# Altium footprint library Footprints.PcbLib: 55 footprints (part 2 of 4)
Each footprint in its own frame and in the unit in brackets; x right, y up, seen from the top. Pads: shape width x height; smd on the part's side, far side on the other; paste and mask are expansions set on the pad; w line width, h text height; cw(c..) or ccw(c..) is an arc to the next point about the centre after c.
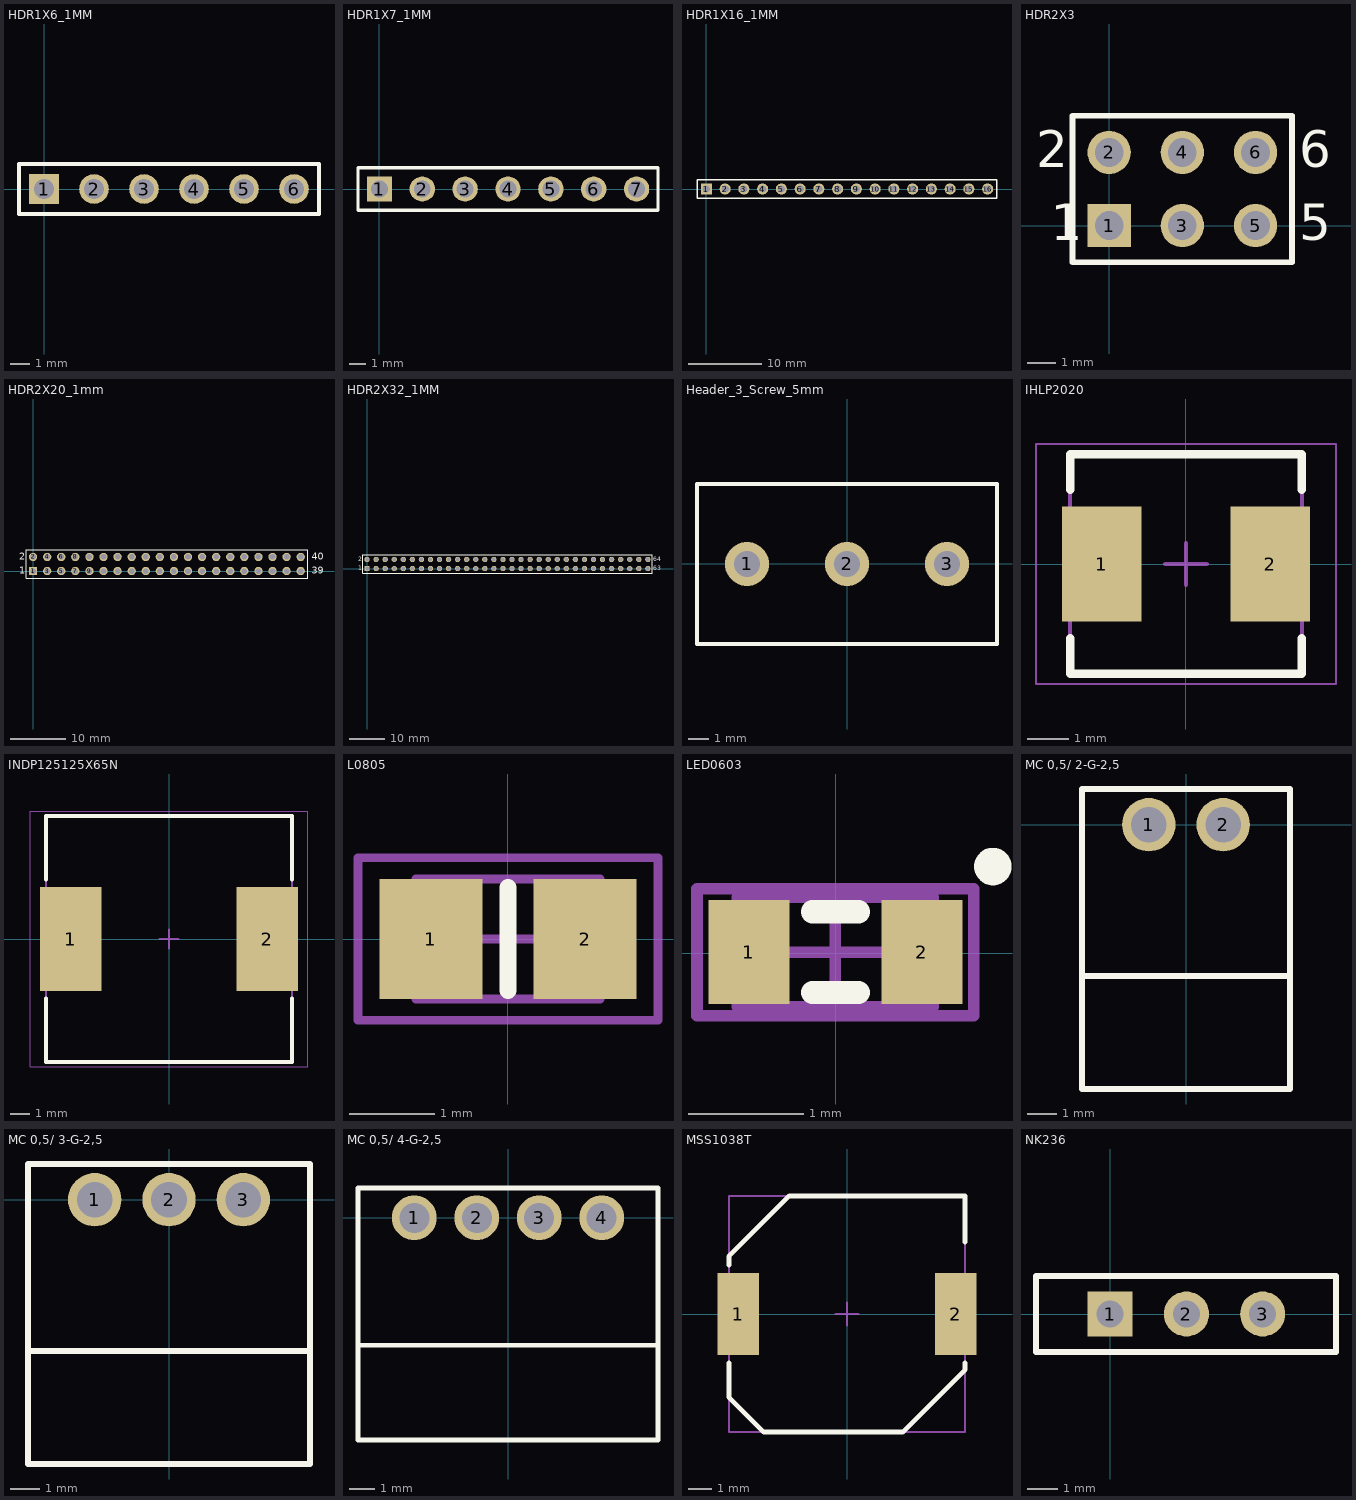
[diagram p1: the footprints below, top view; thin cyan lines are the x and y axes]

## HDR1X6_1MM [mm] "Connector; Header; 6 Position"
pads (6):
  rect 1.5x1.5 hole 1: 1(0,0)
  round 1.5 hole 1: 2(2.54,0) 3(5.08,0) 4(7.62,0) 5(10.16,0) 6(12.7,0)
Top Overlay:
  lines w0.2: -1.27,-1.27 13.97,-1.27 13.97,1.27 -1.27,1.27 -1.27,-1.27

## HDR1X7_1MM [mm] "Connector; Header; 7 Position"
pads (7):
  rect 1.5x1.5 hole 1: 1(0,0)
  round 1.5 hole 1: 2(2.54,0) 3(5.08,0) 4(7.62,0) 5(10.16,0) 6(12.7,0) 7(15.24,0)
Top Overlay:
  lines w0.2: -1.27,-1.27 16.51,-1.27 16.51,1.27 -1.27,1.27 -1.27,-1.27

## HDR1X16_1MM [mm] "Connector; Header; 16 Position"
pads (16):
  rect 1.5x1.5 hole 1: 1(0,0)
  round 1.5 hole 1: 2(2.54,0) 3(5.08,0) 4(7.62,0) 5(10.16,0) 6(12.7,0) 7(15.24,0) 8(17.78,0) 9(20.32,0) 10(22.86,0) 11(25.4,0) 12(27.94,0) 13(30.48,0) 14(33.02,0) 15(35.56,0) 16(38.1,0)
Top Overlay:
  lines w0.2: -1.27,-1.27 -1.27,1.27 0.635,1.27 39.37,1.27 39.37,-1.27 -1.27,-1.27

## HDR2X3 [mm] "Connector; Header; 3x2 Position"
pads (6):
  rect 1.5x1.5 hole 1: 1(0,0)
  round 1.5 hole 1: 2(0,2.54) 3(2.54,0) 4(2.54,2.54) 5(5.08,0) 6(5.08,2.54)
Top Overlay:
  lines w0.2: 1.482,-1.27 6.35,-1.27 ; 6.35,-1.27 6.35,3.81 -1.27,3.81 -1.27,-1.27 6.35,-1.27
  text "6" at 6.604,2.032 h1.27
  text "5" at 6.604,-0.508 h1.27
  text "2" at -2.54,2.032 h1.27
  text "1" at -2.032,-0.508 h1.27
3D body: height 8.45, standoff -2.53, extent -1.265,-1.365 6.355,3.715

## HDR2X20_1mm [mm] "1mm drill hole Connector; Header; 20x2 Position"
pads (40):
  rect 1.5x1.5 hole 1: 1(0,0)
  round 1.5 hole 1: 2(0,2.54) 3(2.54,0) 4(2.54,2.54) 5(5.08,0) 6(5.08,2.54) 7(7.62,0) 8(7.62,2.54) 9(10.16,0) 10(10.16,2.54) 11(12.7,0) 12(12.7,2.54) 13(15.24,0) 14(15.24,2.54) 15(17.78,0) 16(17.78,2.54) 17(20.32,0) 18(20.32,2.54) 19(22.86,0) 20(22.86,2.54) 21(25.4,0) 22(25.4,2.54) 23(27.94,0) 24(27.94,2.54) 25(30.48,0) 26(30.48,2.54) 27(33.02,0) 28(33.02,2.54) 29(35.56,0) 30(35.56,2.54) 31(38.1,0) 32(38.1,2.54) 33(40.64,0) 34(40.64,2.54) 35(43.18,0) 36(43.18,2.54) 37(45.72,0) 38(45.72,2.54) 39(48.26,0) 40(48.26,2.54)
Top Overlay:
  lines w0.2: -1.27,-1.27 49.53,-1.27 49.53,3.81 -1.27,3.81 -1.27,-1.27
  text "1" at -2.54,-0.508 h1.27
  text "2" at -2.54,2.032 h1.27
  text "40" at 50.292,2.032 h1.27
  text "39" at 50.292,-0.508 h1.27

## HDR2X32_1MM [mm] "Connector; Header; 30x2 Position"
pads (64):
  rect 1.5x1.5 hole 1: 1(0,0)
  round 1.5 hole 1: 2(0,2.54) 3(2.54,0) 4(2.54,2.54) 5(5.08,0) 6(5.08,2.54) 7(7.62,0) 8(7.62,2.54) 9(10.16,0) 10(10.16,2.54) 11(12.7,0) 12(12.7,2.54) 13(15.24,0) 14(15.24,2.54) 15(17.78,0) 16(17.78,2.54) 17(20.32,0) 18(20.32,2.54) 19(22.86,0) 20(22.86,2.54) 21(25.4,0) 22(25.4,2.54) 23(27.94,0) 24(27.94,2.54) 25(30.48,0) 26(30.48,2.54) 27(33.02,0) 28(33.02,2.54) 29(35.56,0) 30(35.56,2.54) 31(38.1,0) 32(38.1,2.54) 33(40.64,0) 34(40.64,2.54) 35(43.18,0) 36(43.18,2.54) 37(45.72,0) 38(45.72,2.54) 39(48.26,0) 40(48.26,2.54) 41(50.8,0) 42(50.8,2.54) 43(53.34,0) 44(53.34,2.54) 45(55.88,0) 46(55.88,2.54) 47(58.42,0) 48(58.42,2.54) 49(60.96,0) 50(60.96,2.54) 51(63.5,0) 52(63.5,2.54) 53(66.04,0) 54(66.04,2.54) 55(68.58,0) 56(68.58,2.54) 57(71.12,0) 58(71.12,2.54) 59(73.66,0) 60(73.66,2.54) 61(76.2,0) 62(76.2,2.54) 63(78.74,0) 64(78.74,2.54)
Top Overlay:
  lines w0.2: -1.27,-1.27 79.9,-1.27 79.9,3.81 -1.27,3.81 -1.27,-1.27
  text "64" at 80.312,2.032 h1.27
  text "63" at 80.312,-0.508 h1.27
  text "1" at -2.54,-0.508 h1.27
  text "2" at -2.54,2.032 h1.27

## Header_3_Screw_5mm [mm]
pads (3):
  round 2.2 hole 1.3: 1(-5,0) 2(0,0) 3(5,0)
Top Overlay:
  lines w0.2: -7.5,-4 -7.5,4 7.5,4 7.5,-4 -7.5,-4
Mechanical 13:
  lines w0.1: -7.5,-4 7.5,-4 7.5,4 -7.5,4 -7.5,-4

## IHLP2020 [mm] "Precision Wire Wound Inductor, 2-Leads, Body 5.50x5.20mm, IPC Medium Density"
height 3
pads (2):
  rect 1.915x2.79 smd: 1(-2.037,0) 2(2.038,0)
Top Overlay:
  lines w0.2: -2.8,-1.795 -2.8,-2.65 2.8,-2.65 2.8,-1.795 ; -2.8,1.795 -2.8,2.65 2.8,2.65 2.8,1.795
Mechanical 13:
  lines w0.1: -2.8,-2.65 2.8,-2.65 2.8,2.65 -2.8,2.65 -2.8,-2.65
Mechanical 15:
  lines w0.05: -3.625,-2.9 3.625,-2.9 3.625,2.9 -3.625,2.9 -3.625,-2.9
  lines w0.1: -0.5,0 0.5,0 ; 0,-0.5 0,0.5
3D body: height 2.9, standoff -0.2, extent -2.699,-2.698 2.684,2.699

## INDP125125X65N [mm] "Precision Wire Wound Inductor, 2-Leads, Body 12.50x12.50mm, IPC Medium Density"
height 6.5
pads (2):
  rect 3.2x5.4 smd: 1(-5.1,0) 2(5.1,0)
Top Overlay:
  lines w0.2: -6.4,-3.1 -6.4,-6.4 6.4,-6.4 6.4,-3.1 ; -6.4,3.1 -6.4,6.4 6.4,6.4 6.4,3.1
Mechanical 13:
  lines w0.1: -6.4,-6.4 6.4,-6.4 6.4,6.4 -6.4,6.4 -6.4,-6.4
Mechanical 15:
  lines w0.05: -7.225,-6.65 7.225,-6.65 7.225,6.65 -7.225,6.65 -7.225,-6.65
  lines w0.1: -0.5,0 0.5,0 ; 0,-0.5 0,0.5
3D body: height 4.6, standoff -0.2, extent -6.1,-6.1 6.1,6.1

## L0805 [mm] "Chip Resistor, Body 2.0x1.2mm, IPC Medium Density"
height 0.7
pads (2):
  rect 1.2x1.4 smd: 1(-0.9,0) 2(0.9,0)
Top Overlay:
  lines w0.2: 0,-0.6 0,0.6
Mechanical 13:
  lines w0.1: -1.075,-0.7 -1.075,0.7 1.075,0.7 1.075,-0.7 -1.075,-0.7
Mechanical 15:
  lines w0.1: -0.5,0 0.5,0 ; 0,-0.5 0,0.5 ; -1.75,-0.95 -1.75,0.95 1.75,0.95 1.75,-0.95 -1.75,-0.95
3D body: height 1.3, standoff 0, extent -1,-0.6 1,0.6

## LED0603 [mm]
height 0.9
pads (2):
  rect 0.7x0.9 smd: 1(-0.751,0.008) 2(0.749,0.008)
Top Overlay:
  circle w0.254: c1.365,0.75 r0.035
  lines w0.2: -0.201,-0.342 0.199,-0.342 ; -0.201,0.358 0.199,0.358
Mechanical 13:
  lines w0.1: -0.851,-0.467 -0.851,0.483 0.849,0.483 0.849,-0.467 -0.851,-0.467
Mechanical 15:
  lines w0.1: -0.476,0.008 0.474,0.008 ; -0.001,-0.467 -0.001,0.483 ; -1.201,-0.542 -1.201,0.558 1.199,0.558 1.199,-0.542 -1.201,-0.542
3D body: height 0.5, standoff 0, extent -0.801,-0.392 0.799,0.408

## MC 0,5/ 2-G-2,5 [mm] "Phoenix Contacts 2 pin header - pitch 2.5mm"
height 8.1
pads (2):
  round 1.8 hole 1.2: 1(-1.25,0) 2(1.25,0)
Top Overlay:
  lines w0.2: -3.5,-5.1 3.5,-5.1 ; -3.5,-8.9 -3.5,1.2 3.5,1.2 3.5,-8.9 -3.5,-8.9
Mechanical 13:
  lines w0.1: -3.5,-8.9 3.5,-8.9 3.5,1.2 -3.5,1.2 -3.5,-8.9
3D body: height 8.1, standoff -3.5, extent -3.45,-8.9 3.45,1.2

## MC 0,5/ 3-G-2,5 [mm] "Phoenix Contacts 3 pin header - pitch 2.5mm"
height 8.1
pads (3):
  round 1.8 hole 1.2: 1(-2.5,0) 2(0,0) 3(2.5,0)
Top Overlay:
  lines w0.2: -4.75,-5.1 4.7,-5.1 ; 4.7,-8.9 -4.75,-8.9 -4.75,1.2 4.75,1.2 4.75,-8.9
Mechanical 13:
  lines w0.1: -4.75,-8.9 4.7,-8.9 4.7,1.2 -4.75,1.2 -4.75,-8.9
3D body: height 8.1, standoff -3.5, extent -4.7,-8.9 4.7,1.2

## MC 0,5/ 4-G-2,5 [mm] "Phoenix Contacts 4 pin header - pitch 2.5mm"
height 8.1
pads (4):
  round 1.8 hole 1.2: 1(-3.75,0) 2(-1.25,0) 3(1.25,0) 4(3.75,0)
Top Overlay:
  lines w0.2: -6,-5.1 6,-5.1 ; -6,-8.9 6,-8.9 6,1.2 -6,1.2 -6,-8.9
Mechanical 13:
  lines w0.1: -6,-8.9 -6,1.2 6,1.2 6,-8.9 -6,-8.9
3D body: height 8.1, standoff -3.5, extent -5.95,-8.9 5.95,1.2

## MSS1038T [mm] "Precision Wire Wound Inductor, 2-Leads, Coilcraft MSS2038T 10x10mm"
height 4
pads (2):
  rect 1.78x3.56 smd: 1(-4.7,0) 2(4.7,0)
Top Overlay:
  lines w0.2: -5.1,-2.1 -5.1,-3.6 -3.6,-5.1 2.4,-5.1 5.1,-2.4 5.1,-2.1 ; -5.1,2.1 -5.1,2.5 -2.5,5.1 5.1,5.1 5.1,3.1
Mechanical 13:
  lines w0.1: -5.1,-5.1 5.1,-5.1 ; -5.1,-5.1 -5.1,5.1 5.1,5.1 5.1,-5.1 ; -5.1,-5.1 5.1,-5.1
Mechanical 15:
  lines w0.1: -0.5,0 0.5,0 ; 0,-0.5 0,0.5
3D body: height 3.9, standoff -0.1, extent -5.15,-5.1 5.15,5.1

## NK236 [mm] "Miniatrue Switch; 3 Position"
pads (3):
  rect 1.5x1.5 hole 0.9: 1(0,0)
  round 1.5 hole 0.9: 2(2.54,0) 3(5.08,0)
Top Overlay:
  lines w0.2: -2.475,-1.27 -2.475,1.27 7.525,1.27 7.525,-1.27 -2.475,-1.27
3D body: height 6.1, standoff -5.4, extent -2.46,-1.3 7.54,1.3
